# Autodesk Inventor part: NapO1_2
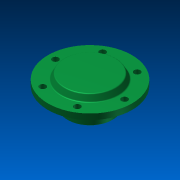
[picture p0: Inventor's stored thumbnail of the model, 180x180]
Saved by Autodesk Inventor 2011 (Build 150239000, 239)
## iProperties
Created: 2011-05
Part Number: NapO1_2
Document SubType Name: Modeling
Designer: 904Chiaki
Density: 1 g/cm^3
Mass: 244.351 g
Surface Area: 590.801 cm^2
Volume: 244.351 cm^3
Author: 904Chiaki
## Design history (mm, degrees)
sketch "Sketch1"
  geometry: C1 r 74 at (-17.134, 0); 1 further point
  constraints: 1 centre point
  dimensions: "d0" = 148 diameter of C1
extrude "Extrusion1" new body sketch "Sketch1" distance "d1" = 10; taper "d2" = 0 deg
sketch "Sketch2"
  geometry: C1 r 74 at (0, 0) reference; C2 r 50 at (0, 0); 1 further point
  constraints: 1 centre point, 1 coincident
  dimensions: "d3" = 100 diameter of C2
extrude "Extrusion2" join sketch "Sketch2" distance "d4" = 10; taper "d5" = 0 deg
sketch "Sketch3"
  geometry: C1 r 74 at (0, 0) reference; C2 r 35 at (0, 0); 1 further point
  constraints: 1 centre point, 1 coincident
  dimensions: "d6" = 70 diameter of C2
extrude "Extrusion3" cut sketch "Sketch3" distance "d7" = 8; taper "d8" = 0 deg
chamfer "Chamfer1" distance "d10" = 10; stored, may be unused: second distance "d11" = 5, angle "d12" = 45 deg
sketch "Sketch4"
  geometry: C1 r 35 at (0, 0) reference; C2 r 74 at (0, 0) reference; C3 r 39 at (0, 0); 1 further point
  constraints: 1 centre point, 1 coincident
  dimensions: "d13" = 78 diameter of C3
extrude "Extrusion4" join sketch "Sketch4" distance "d14" = 2; taper "d15" = 0 deg
sketch "Sketch5"
  geometry: C1 r 35 at (0, 0) reference; C2 r 39 at (0, 0) reference; C3 r 40 at (0, 0); 1 further point
  constraints: 1 centre point, 1 coincident
  dimensions: "d16" = 80 diameter of C3
extrude "Extrusion5" join sketch "Sketch5" distance "d17" = 30.75; taper "d18" = 0 deg
fillet "Fillet1" dims "d23" = 2
fillet "Fillet2" dims "d24" = 2
chamfer "Chamfer2" distance "d25" = 1; stored, may be unused: second distance "d26" = 5, angle "d27" = 45 deg
workplane "Work Plane2"
  workaxis "Work Axis2"
workpoint "Work Point1"
workpoint "Work Point2"
workpoint "Work Point3"
workpoint "Work Point4"
workpoint "Work Point5"
workpoint "Work Point6"
node "Hole2"
body "Solid1"
sketch "Sketch9"
  geometry: 6 further points
hole "Hole1" sketch "Sketch9" diameter "d35" = 11; stored, may be unused: countersink angle "d39" = 90 deg, drill point angle "d41" = 0 deg; dims "d36" = 6, "d37" = 4, "d38" = 2, "d40" = 8
other parameters: "d28" = 90 deg
